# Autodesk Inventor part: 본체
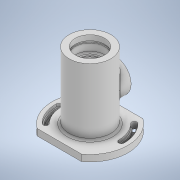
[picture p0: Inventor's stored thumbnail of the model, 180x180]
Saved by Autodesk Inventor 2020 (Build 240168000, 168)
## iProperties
Created: 2022-05
Part Number: 본체
Material: 일반
Document SubType Name: Modeling
Designer: Student
Density: 1 g/cm^3
Appearance: 기본값
Author: Student
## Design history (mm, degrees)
sketch "스케치5"
  geometry: L1 (33.985, -47)-(-33.985, -47); L2 (-33.985, 47)-(33.985, 47); A1 r 58 centre (0, 0) between (33.985, -47) and (33.985, 47); A2 r 58 centre (0, 0) between (-33.985, 47) and (-33.985, -47); 1 further point
  constraints: 4 end point, 4 point on circle, 2 centre point, 1 coincident, 1 concentric, 1 horizontal, 1 parallel
  dimensions: "d62" = 58 radius of A2; "d63" = 94 distance between parallel lines of L1 L2; "d64" = 47 distance from line of L2 point (0, 0)
extrude "돌출1" new body sketch "스케치5" distance "d65" = 10; taper "d66" = 0 deg
sketch "스케치6"
  geometry: C1 r 36 at (0, 0); 1 further point
  constraints: 1 centre point, 1 coincident
  dimensions: "d67" = 36 radius of C1
extrude "돌출2" join sketch "스케치6" distance "d68" = 3; taper "d69" = 0 deg
sketch "스케치8"
  geometry: C1 r 32 at (0, 0); 1 further point
  constraints: 1 centre point, 1 coincident
  dimensions: "d70" = 64 diameter of C1
extrude "돌출3" join sketch "스케치8" distance "d71" = 102; taper "d72" = 0 deg
sketch "스케치10"
  geometry: L1 (112, -22.5)-(104, -22.5); L2 (112, -32)-(112, 32) reference; L3 (104, -22.5)-(104, -24); L4 (104, -24)-(101, -24); L5 (101, -24)-(101, -22.5); L6 (101, -22.5)-(90, -22.5); L7 (90, -22.5)-(90, -17.5); L8 (90, -17.5)-(87.75, -17.5); L9 (87.75, -17.5)-(87.75, -18.5); L10 (87.75, -18.5)-(86, -18.5); L11 (86, -18.5)-(86, -17.5); L12 (86, -17.5)-(75, -17.5); L13 (75, -17.5)-(75, -27); L14 (0, 0)-(159.054, 0); L15 (75, -27)-(37, -27); L16 (37, -27)-(37, -20); L17 (37, -20)-(26, -20); L18 (26, -20)-(26, -15); L19 (26, -15)-(21, -15); L20 (21, -15)-(21, -11); L21 (21, -11)-(17.3, -11); L22 (17.3, -11)-(17.3, -15); L23 (17.3, -15)-(10, -15); L24 (10, -15)-(10, -20); L25 (10, -20)-(-3, -30); L26 (112, -22.5)-(112, 0); L27 (-3, 0)-(112, 0); L28 (-3, 36)-(-3, -36) reference; L29 (-3, -30)-(-3, 0); 1 further point
  constraints: 54 end point, 15 perpendicular, 8 point on line, 4 horizontal, 2 vertical, 1 collinear, 1 midpoint, 1 parallel
  dimensions: "d79" = 8 distance between parallel lines of L3 L2; "d80" = 3 distance of L3.end L4.end; "d82" = 22 distance between parallel lines of L7 L2; "d83" = 11 distance of L11.end L12.end; "d84" = 1.75 distance of L9.end L10.end; "d85" = 37 diameter of L10 L14; "d86" = 45 diameter of L1 L14; "d87" = 48 diameter of L4 L14; "d88" = 45 diameter of L6 L14; "d89" = 35 diameter of L8 L14; "d90" = 4 distance between parallel lines of L7 L11; "d91" = 38 distance of L13.end L15.end; "d92" = 11 distance between parallel lines of L18 L16; "d93" = 5 distance of L18.end L19.end; "d95" = 60 diameter of L25.end L14; "d96" = 40 diameter of L24.end L14; "d97" = 30 diameter of L23 L14; "d98" = 22 diameter of L21 L14; "d99" = 7.3 distance between parallel lines of L22 L24; "d100" = 54 diameter of L15 L14; "d102" = 47.0541 distance from line of L14.end L2; "d105" = 13 distance between parallel lines of L24 L28
revolve "회전1" sketch "스케치10" stored, may be unused: angle "d104" = 90 deg
fillet "모깎기1" dims "d106" = 0.5
sketch "스케치11"
  geometry: L1 (0, 0)-(48, 0); L2 (0, 0)-(33.941, 33.941); L3 (0, 0)-(70.158, 0); C1 r 14.5 at (0, 0) reference; A1 r 48 centre (0, 0) between (48, 0) and (33.941, 33.941); A2 r 52 centre (0, 0) between (52, 0) and (36.77, 36.77); A3 r 44 centre (0, 0) between (44, 0) and (31.113, 31.113); A4 r 4 centre (48, 0) between (44, 0) and (52, 0); A5 r 4 centre (33.941, 33.941) between (36.77, 36.77) and (31.113, 31.113); 1 further point
  constraints: 10 point on circle, 6 end point, 5 centre point, 4 tangent, 1 coincident, 1 horizontal, 1 point on line
  dimensions: "d107" = 4 radius of A4; "d108" = 48 radius of A1; "d109" = 45 deg angle of L1 L2
extrude "돌출4" cut sketch "스케치11" distance "d110" = 4.4; taper "d111" = 0 deg
sketch "스케치12"
  geometry: A1 r 4 centre (33.941, 33.941) between (36.77, 36.77) and (31.113, 31.113) reference; A2 r 4 centre (48, 0) between (44, 0) and (52, 0) reference; A3 r 48 centre (0, 0) between (48, 0) and (33.941, 33.941); A4 r 50.25 centre (0, 0) between (50.25, 0) and (35.532, 35.532); A5 r 45.75 centre (0, 0) between (45.75, 0) and (32.35, 32.35); A6 r 2.25 centre (48, 0) between (45.75, 0) and (50.25, 0); A7 r 2.25 centre (33.941, 33.941) between (35.532, 35.532) and (32.35, 32.35); 1 further point
  constraints: 10 point on circle, 5 centre point, 4 tangent, 1 coincident
  dimensions: "d112" = 4.5 diameter of A6
extrude "돌출5" cut sketch "스케치12" distance "d113" = 4.4; taper "d114" = 0 deg
sketch "스케치13"
  geometry: C1 r 4 at (33.941, 33.941); A1 r 50.25 centre (0, 0) between (50.25, 0) and (35.532, 35.532) reference; A2 r 2.25 centre (33.941, 33.941) between (35.532, 35.532) and (32.35, 32.35) reference; A3 r 45.75 centre (0, 0) between (45.75, 0) and (32.35, 32.35) reference; A4 r 2.25 centre (48, 0) between (45.75, 0) and (50.25, 0) reference; 1 further point
  constraints: 1 centre point, 1 coincident
  dimensions: "d115" = 8 diameter of C1
extrude "돌출6" cut sketch "스케치13" extent not by distance; stored distance "d116" = 4.4; taper "d117" = 0 deg
node "작업 평면1"
sketch "스케치14"
  geometry: L1 (32, 112)-(-32, 112) reference; L2 (33.985, 0)-(-33.985, 0) reference; C1 r 25 at (0, 56); 2 further points
  constraints: 1 centre point, 1 midpoint, 1 vertical alignment
  dimensions: "d122" = 50 diameter of C1; "d123" = 56 distance from line of C1.centre L1
extrude "돌출7" join sketch "스케치14" stored distance "d113" = 4.4; stored distance "d124" = 4.4; taper "d125" = 0 deg
sketch "스케치15"
  geometry: C1 r 25 at (0, 56) reference; C2 r 16 at (0, 56); 1 further point
  constraints: 1 centre point, 1 coincident
  dimensions: "d126" = 32 diameter of C2
extrude "돌출9" cut sketch "스케치15" stored distance "d113" = 4.4; stored distance "d129" = 4.4; taper "d130" = 0 deg
sketch "스케치16"
  geometry: C1 r 16 at (0, 0) reference; 2 further points
  constraints: 1 horizontal alignment
  dimensions: "d131" = 20.5 distance of point (20.5, 0) C1.centre
hole "구멍1" sketch "스케치16" at (20.5, 0) diameter "d132" = 2.459; stored, may be unused: countersink angle "d136" = 90 deg, drill point angle "d138" = 118 deg; dims "d133" = 6, "d134" = 28, "d135" = 4, "d137" = 8
fillet "모깎기2" dims "d142" = 3
chamfer "모따기1" distance "d143" = 1; stored, may be unused: second distance "d144" = 2, angle "d145" = 30 deg
fillet "모깎기3" dims "d146" = 3
node "솔리드1"
pattern_circular "원형 패턴1" dims angle "d119" = 360 deg
pattern_circular "원형 패턴2" dims angle "d140" = 360 deg
node "투영된 루프1"
feature "A9D066F2-1C7D-4E18-AEED-F7BC21143FA4" dims "d132" = 2.459, "d133" = 6, "d134" = 28, "d135" = 4, "d136" = 90 deg, "d137" = 8, "d138" = 118 deg
other parameters: "d16" = 4, "d56" = 58, "d61" = 58, "d121" = -38
